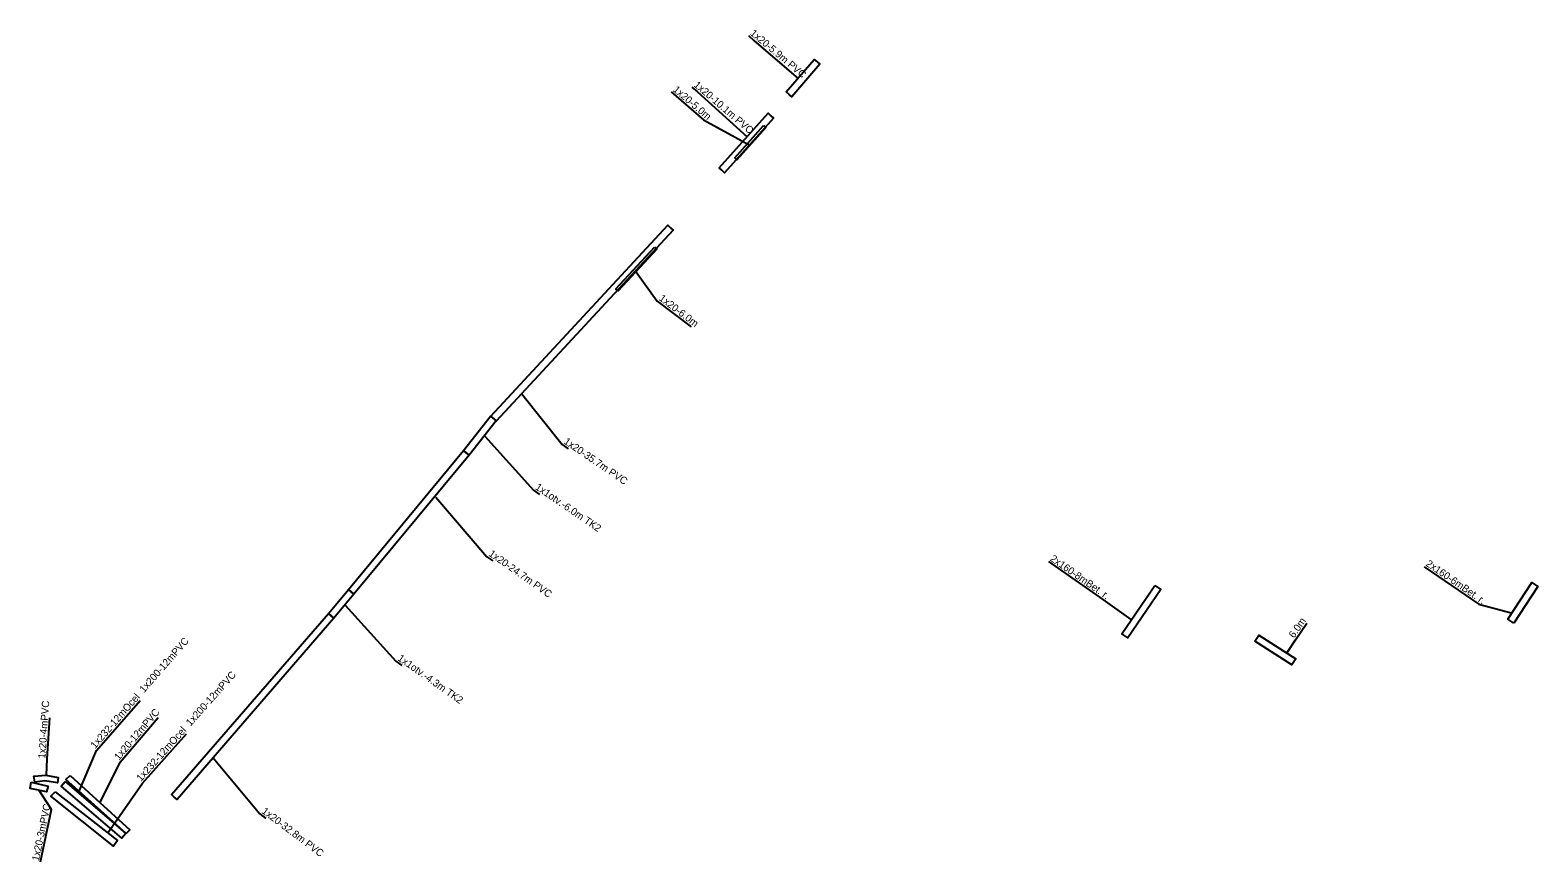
# Model space of a CAD drawing. Extents: x -742805 to -742598, y -1054562 to -1054448.
import ezdxf

# ---------------------------------------------------------------- set-up
doc = ezdxf.new("R2010")
doc.units = 0
doc.layers.add('Chránička', color=7, linetype='Continuous')
doc.layers.add('ST_CHRANICKA_POPIS', color=7, linetype='Continuous')

msp = doc.modelspace()

# ---------------------------------------------------------------- linework, layer by layer
at = {"layer": 'Chránička'}
for points in [[(-742700.559, -1054456.43), (-742700.938, -1054456.104), (-742697.102, -1054451.642), (-742696.723, -1054451.968), (-742696.344, -1054452.294), (-742700.18, -1054456.756), (-742700.559, -1054456.43)], [(-742709.783, -1054466.83), (-742710.155, -1054466.495), (-742703.425, -1054459.019), (-742703.053, -1054459.354), (-742702.681, -1054459.689), (-742709.411, -1054467.165), (-742709.783, -1054466.83)], [(-742704.059, -1054460.699), (-742703.76, -1054460.965), (-742707.698, -1054465.377), (-742707.997, -1054465.111), (-742704.059, -1054460.699)], [(-742741.076, -1054500.818), (-742741.442, -1054500.478), (-742717.177, -1054474.354), (-742716.811, -1054474.694), (-742716.445, -1054475.034), (-742740.71, -1054501.158), (-742741.076, -1054500.818)], [(-742718.986, -1054477.354), (-742718.694, -1054477.627), (-742723.988, -1054483.328), (-742724.317, -1054483.049), (-742718.986, -1054477.354)], [(-742744.796, -1054505.51), (-742745.188, -1054505.199), (-742741.468, -1054500.507), (-742741.076, -1054500.818), (-742740.684, -1054501.129), (-742744.404, -1054505.821), (-742744.796, -1054505.51)], [(-742760.56, -1054524.566), (-742760.945, -1054524.247), (-742745.181, -1054505.191), (-742744.796, -1054505.51), (-742744.411, -1054505.829), (-742760.175, -1054524.885), (-742760.56, -1054524.566)], [(-742601.26, -1054528.818), (-742602.096, -1054528.27), (-742598.808, -1054523.251), (-742597.972, -1054523.799), (-742601.26, -1054528.818)], [(-742763.301, -1054527.843), (-742763.685, -1054527.522), (-742760.944, -1054524.245), (-742760.56, -1054524.566), (-742760.176, -1054524.887), (-742762.917, -1054528.164), (-742763.301, -1054527.843)], [(-742650.459, -1054523.675), (-742649.631, -1054524.237), (-742654.126, -1054530.855), (-742654.954, -1054530.293), (-742650.459, -1054523.675)], [(-742784.797, -1054552.643), (-742785.175, -1054552.316), (-742763.679, -1054527.516), (-742763.301, -1054527.843), (-742762.923, -1054528.17), (-742784.419, -1054552.97), (-742784.797, -1054552.643)], [(-742636.736, -1054531.306), (-742636.196, -1054530.464), (-742631.149, -1054533.709), (-742631.689, -1054534.551), (-742636.736, -1054531.306)], [(-742803.913, -1054550.593), (-742804.041, -1054549.779), (-742802.401, -1054549.643), (-742800.691, -1054549.987), (-742800.815, -1054550.69), (-742802.509, -1054550.448), (-742803.913, -1054550.593)], [(-742799.042, -1054549.71), (-742790.892, -1054557.15), (-742791.404, -1054557.639), (-742799.646, -1054550.24), (-742799.042, -1054549.71)], [(-742804.406, -1054550.63), (-742802.096, -1054551.17), (-742802.316, -1054551.949), (-742804.542, -1054551.464), (-742804.406, -1054550.63)], [(-742801.106, -1054551.949), (-742792.587, -1054558.58), (-742793.141, -1054559.359), (-742801.701, -1054552.509), (-742801.106, -1054551.949)], [(-742799.743, -1054550.51), (-742791.433, -1054557.66), (-742791.99, -1054558.299), (-742800.305, -1054551.156), (-742799.743, -1054550.51)]]:
    msp.add_lwpolyline(points, close=True, dxfattribs=at)
at = {"layer": 'ST_CHRANICKA_POPIS'}
for points in [[(-742706.141, -1054448.392), (-742705.375, -1054449.036), (-742699.266, -1054454.283)], [(-742716.717, -1054456.107), (-742712.284, -1054459.898), (-742706.043, -1054463.322)], [(-742713.864, -1054455.455), (-742713.105, -1054456.107), (-742706.32, -1054462.229)], [(-742721.536, -1054480.686), (-742718.624, -1054484.732), (-742713.985, -1054488.269)], [(-742737.229, -1054497.383), (-742731.666, -1054504.382), (-742730.842, -1054504.948)], [(-742742.267, -1054503.247), (-742735.582, -1054510.634), (-742734.758, -1054511.201)], [(-742748.951, -1054511.593), (-742741.959, -1054519.736), (-742741.142, -1054520.313)], [(-742665.027, -1054520.418), (-742657.592, -1054525.593), (-742653.736, -1054528.32)], [(-742613.553, -1054521.12), (-742606.073, -1054526.231), (-742601.635, -1054527.407)], [(-742761.391, -1054526.383), (-742754.436, -1054534.056), (-742753.619, -1054534.633)], [(-742632.339, -1054532.857), (-742631.167, -1054531.105), (-742629.604, -1054528.848)], [(-742797.921, -1054552.068), (-742795.451, -1054546.267), (-742789.486, -1054539.449)], [(-742802.318, -1054549.637), (-742802.216, -1054547.433), (-742801.827, -1054541.819)], [(-742794.916, -1054553.317), (-742792.188, -1054547.858), (-742786.982, -1054541.745)], [(-742793.892, -1054557.562), (-742789.169, -1054550.764), (-742783.128, -1054544.013)], [(-742779.446, -1054547.265), (-742773.062, -1054554.969), (-742772.264, -1054555.571)], [(-742803.102, -1054561.519), (-742801.601, -1054554.332), (-742803.329, -1054551.75)]]:
    msp.add_lwpolyline(points, dxfattribs=at)

# ---------------------------------------------------------------- texts
for s, rotation, p in [('1x20-5.9m PVC', 319.97161, (-742705.98, -1054448.201)), ('1x20-10.1m PVC', 319.32141, (-742713.701, -1054455.266)), ('1x20-5.0m', 319.46622, (-742716.555, -1054455.917)), ('1x20-6.0m', 322.67499, (-742718.473, -1054484.534)), ('1x20-35.7m PVC', 325.51342, (-742731.524, -1054504.176)), ('1x1otv.-6.0m TK2', 325.51435, (-742735.44, -1054510.428)), ('1x20-24.7m PVC', 324.77535, (-742741.815, -1054519.532)), ('2x160-8mBet. r.', 325.15672, (-742664.884, -1054520.213)), ('2x160-6mBet. r.', 325.6577, (-742613.412, -1054520.914)), ('6.0m', 55.2914, (-742631.373, -1054530.963)), ('1x232-12mOcel  1x200-12mPVC', 48.81764, (-742795.639, -1054546.102)), ('1x1otv.-4.3m TK2', 324.77535, (-742754.292, -1054533.852)), ('1x232-12mOcel  1x200-12mPVC', 48.17468, (-742789.356, -1054550.597)), ('1x20-4mPVC', 86.03456, (-742802.466, -1054547.416)), ('1x20-12mPVC', 49.57605, (-742792.379, -1054547.696)), ('1x20-3mPVC', 78.20352, (-742803.346, -1054561.468)), ('1x20-32.8m PVC', 322.94604, (-742772.912, -1054554.769))]:
    msp.add_text(s, height=1, rotation=rotation, dxfattribs=at).set_placement(p)

doc.saveas('drawing.dxf')
